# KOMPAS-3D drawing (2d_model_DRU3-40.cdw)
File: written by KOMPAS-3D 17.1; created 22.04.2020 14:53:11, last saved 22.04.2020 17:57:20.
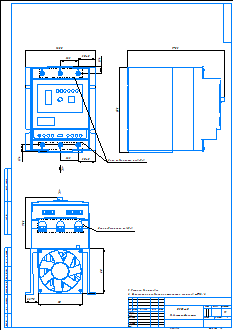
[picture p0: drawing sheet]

Sheet 1: A2, portrait

Title block, sheet 1: name: DRU3-40 / Габаритный чертеж; sheets: 1; sheet format: A2; stored path: E:\Марк\DRU3\DRU3-XX\2d_model_DRU3-40.cdw

Views: Вид по стрелке 4
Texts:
  Пользователь Windows
  HHT45ЙўИИЖч_40A
  100AµзБ¦µчХыЖчЙПёЗ(2014.5.12РЮёД)
  µзБ¦µчХыЖчРэЕҐ
Dimensions and other numbers on the sheet: 1:1; 1; 100AµзБ¦µчХыЖчµЧЧщ; 100AµзБ¦µчХыЖчЅУПЯЧщ; 100AµзБ¦µчХыЖчЅУПЯЖ¬; 80·з»ъ; 45AµзБ¦µчХыЖч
